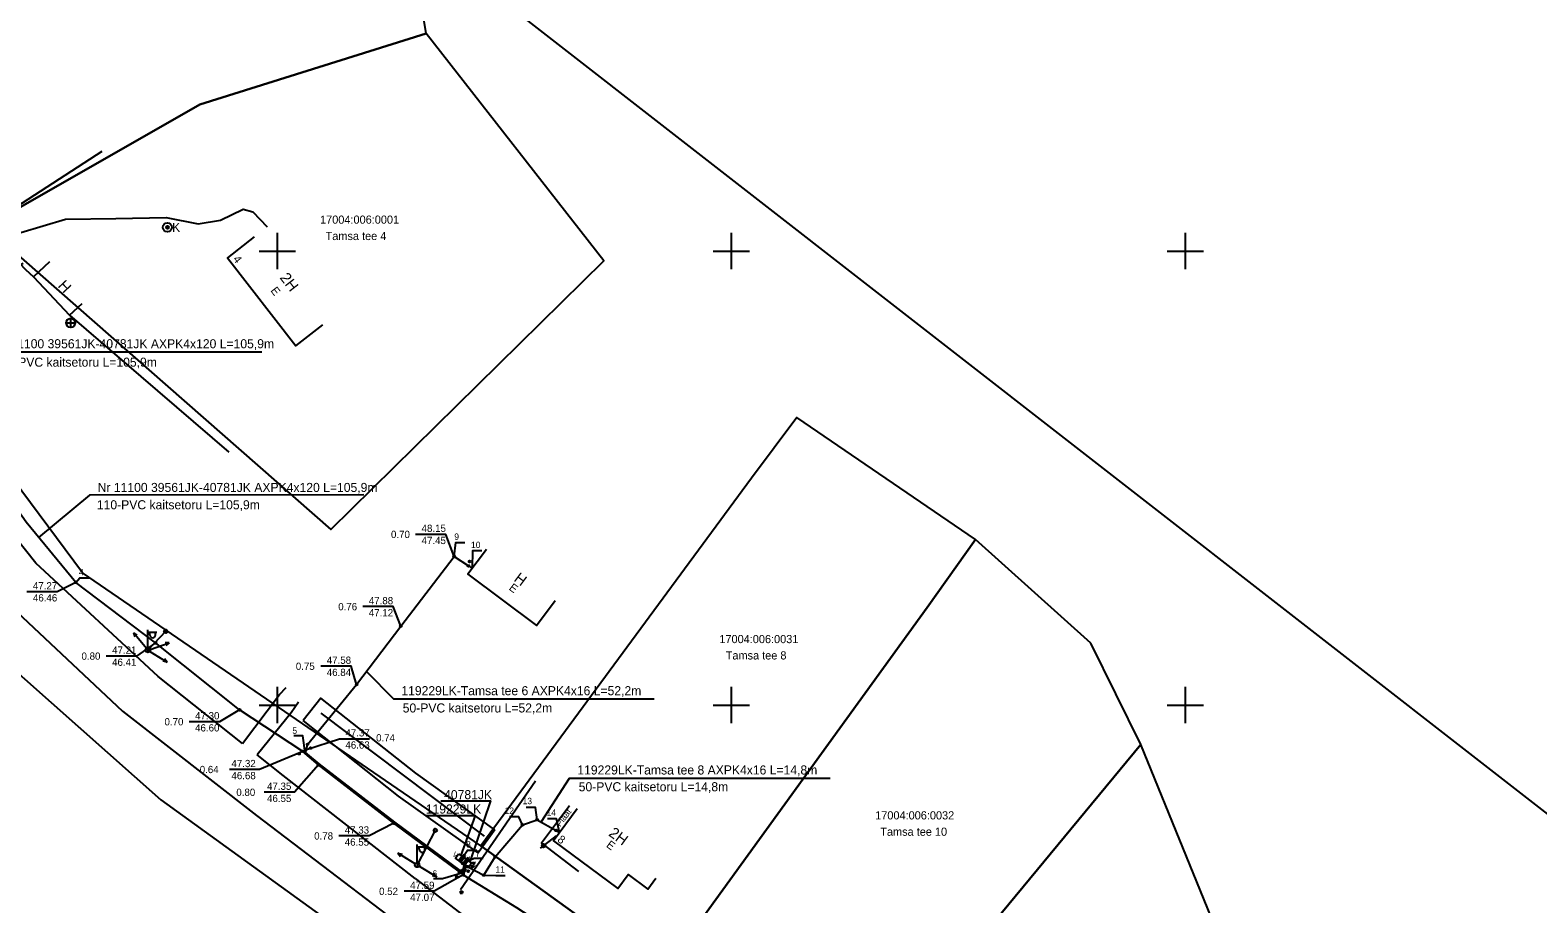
# Model space of a CAD drawing. Extents: x 643977 to 644381, y 6457457 to 6457867.
# Drawn here: x 644122.8 to 644288.8, y 6457628.1 to 6457724.3 of the extents above; entities that cross this region are included whole.
import ezdxf

# ---------------------------------------------------------------- set-up
doc = ezdxf.new("R2010")
doc.units = 0
for name, color, linetype in [('004 MPP EE @ 1 (1)', 7, 'Continuous'), ('005 MPO EE @ 1 (1)', 7, 'Continuous'), ('005 MPO EE @ 1 (2)', 7, 'Continuous'), ('007 PIIR EE', 7, 'Continuous'), ('007 PIIR1 EE', 7, 'Continuous'), ('010 TXT EE', 7, 'Continuous'), ('MOOTMPUNKT', 7, 'Continuous'), ('TEE', 7, 'Continuous'), ('TORU_NR', 7, 'Continuous'), ('UUS', 7, 'Continuous'), ('Veeprojekti jooned$0$0_Hoiatustekst', 7, 'Continuous'), ('VORK', 7, 'Continuous'), ('VORMISTUS', 7, 'Continuous'), ('WOUT EE', 7, 'Continuous')]:
    doc.layers.add(name, color=color, linetype=linetype)

msp = doc.modelspace()

# ---------------------------------------------------------------- linework, layer by layer
at = {"layer": '004 MPP EE @ 1 (1)'}
for p, q in [((644127.12, 6457692.94), (644144.69, 6457677.86)), ((644170.16, 6457629.51), (644170.16, 6457629.26)), ((644170.16, 6457629.51), (644170.41, 6457629.51)), ((644170.16, 6457629.26), (644170.41, 6457629.26)), ((644170.41, 6457629.51), (644170.41, 6457629.26))]:
    msp.add_line(p, q, dxfattribs=at)
msp.add_lwpolyline([(644130.68, 6457710.97), (644117.82, 6457702.64), (644119.64, 6457700.77), (644122.27, 6457697.99), (644123.17, 6457697.16)], dxfattribs=at)
at = {"layer": '005 MPO EE @ 1 (1)'}
for p, q in [((644135.76, 6457656.29), (644135.76, 6457658.29)), ((644137.72, 6457658.12), (644135.76, 6457656.04)), ((644135.76, 6457658.04), (644136.76, 6457658.04)), ((644135.99, 6457657.72), (644135.99, 6457658.04)), ((644136.6, 6457657.72), (644136.6, 6457658.04)), ((644167.41, 6457636.2), (644165.42, 6457632.39)), ((644165.42, 6457632.64), (644165.42, 6457634.64)), ((644165.42, 6457634.39), (644166.42, 6457634.39)), ((644165.65, 6457634.07), (644165.65, 6457634.39)), ((644166.26, 6457634.07), (644166.26, 6457634.39)), ((644170.35, 6457633.34), (644170, 6457632.86)), ((644170.57, 6457633.18), (644170.21, 6457632.7)), ((644170.81, 6457633.03), (644170.46, 6457632.55)), ((644171.03, 6457632.87), (644170.68, 6457632.39))]:
    msp.add_line(p, q, dxfattribs=at)
for points in [[(644166.35, 6457637.85), (644171.81, 6457637.85), (644170.19, 6457633.34)], [(644168.02, 6457639.46), (644173.5, 6457639.46), (644171.19, 6457632.63)]]:
    msp.add_lwpolyline(points, dxfattribs=at)
for points in [[(644169.98, 6457633.61), (644170.94, 6457632.9), (644170.58, 6457632.42), (644169.62, 6457633.13)], [(644170.44, 6457633.3), (644171.4, 6457632.6), (644171.05, 6457632.11), (644170.09, 6457632.82)]]:
    msp.add_lwpolyline(points, close=True, dxfattribs=at)
for centre, radius in [((644137.72, 6457658.12), 0.2), ((644135.76, 6457656.04), 0.25), ((644135.76, 6457656.04), 0.0234), ((644167.41, 6457636.2), 0.2), ((644165.42, 6457632.39), 0.25), ((644165.42, 6457632.39), 0.0234)]:
    msp.add_circle(centre, radius, dxfattribs=at)
for centre in [(644136.29, 6457657.72), (644165.96, 6457634.07)]:
    msp.add_arc(centre, 0.306, 180, 0, dxfattribs=at)
at = {"layer": '005 MPO EE @ 1 (2)'}
for points in [[(644146.19, 6457645.77), (644136.9, 6457653.15), (644123.42, 6457665.62), (644113.13, 6457678.52), (644106.19, 6457690.08), (644107.06, 6457690.75), (644119.77, 6457697.52), (644122.01, 6457698.68)], [(644097.36, 6457696.77), (644100.44, 6457690.48), (644108.83, 6457675.73), (644120.12, 6457661.42), (644132.97, 6457649.32), (644147.71, 6457637.83), (644162.19, 6457626.8)], [(644146.19, 6457645.77), (644150.27, 6457651.15), (644150.97, 6457651.94)], [(644152.36, 6457650.33), (644151.52, 6457649.15), (644147.79, 6457644.5)], [(644165.21, 6457630.91), (644150.65, 6457642.23), (644147.79, 6457644.5)], [(644182.18, 6457638.9), (644179.09, 6457634.77), (644183.17, 6457631.65)], [(644165.21, 6457630.91), (644174.34, 6457623.88), (644186.27, 6457614.62), (644201.04, 6457604.98), (644215.29, 6457597.39), (644225.39, 6457591.42), (644240.38, 6457581.38), (644253.47, 6457570.78), (644267.86, 6457559.31)]]:
    msp.add_lwpolyline(points, dxfattribs=at)
at = {"layer": '007 PIIR EE'}
for p, q in [((644134.16, 6457657.96), (644134.33, 6457657.51)), ((644134.16, 6457657.96), (644134.56, 6457657.71)), ((644135.6, 6457656.23), (644134.16, 6457657.96)), ((644136, 6457656.12), (644138.12, 6457656.86)), ((644138.12, 6457656.86), (644137.65, 6457656.85)), ((644138.12, 6457656.86), (644137.74, 6457656.57)), ((644135.98, 6457655.91), (644137.9, 6457654.74)), ((644137.9, 6457654.74), (644137.44, 6457654.85)), ((644137.9, 6457654.74), (644137.59, 6457655.1)), ((644163.29, 6457633.69), (644163.59, 6457633.32)), ((644163.29, 6457633.69), (644163.75, 6457633.58)), ((644165.21, 6457632.52), (644163.29, 6457633.69)), ((644165.64, 6457632.26), (644167.56, 6457631.09)), ((644167.56, 6457631.09), (644167.1, 6457631.2)), ((644167.56, 6457631.09), (644167.25, 6457631.46))]:
    msp.add_line(p, q, dxfattribs=at)
at = {"layer": '007 PIIR1 EE'}
for points in [[(644117.56, 6457701.26), (644118.53, 6457701.57), (644119.51, 6457701.72), (644121.77, 6457702.04), (644126.68, 6457703.53), (644132.24, 6457703.6), (644137.78, 6457703.72), (644141.28, 6457703.01), (644143.77, 6457703.42), (644146.25, 6457704.61), (644147.33, 6457704.32), (644148.9, 6457702.67)], [(644170.75, 6457632.71), (644170.64, 6457632.25), (644170.59, 6457631.82), (644170.29, 6457631.6), (644170.08, 6457631.62), (644162.86, 6457636.99), (644154.53, 6457643.4), (644152.81, 6457644.9), (644145.85, 6457649.47), (644136.59, 6457656.84), (644127.81, 6457663.51), (644122.37, 6457670.16), (644115.89, 6457679.24), (644110.22, 6457687.94), (644105.98, 6457693.61), (644105.49, 6457694.03), (644109.92, 6457695.7), (644115.67, 6457699.15), (644117.04, 6457700.73)], [(644170.75, 6457632.71), (644170.64, 6457632.25), (644170.59, 6457631.82), (644170.29, 6457631.6), (644170.08, 6457631.62), (644162.86, 6457636.99), (644154.53, 6457643.4), (644152.81, 6457644.9), (644145.85, 6457649.47), (644136.59, 6457656.84), (644127.81, 6457663.51), (644122.37, 6457670.16), (644115.89, 6457679.24), (644110.22, 6457687.94), (644105.98, 6457693.61), (644105.57, 6457694.06), (644109.92, 6457695.7), (644115.67, 6457699.15), (644117.04, 6457700.73)], [(644148.31, 6457688.88), (644118.1, 6457688.86), (644110.61, 6457696.12)], [(644159.55, 6457673.14), (644129.34, 6457673.12), (644123.73, 6457668.47)], [(644169.49, 6457666.35), (644168.57, 6457668.8), (644165.24, 6457668.8)], [(644170.75, 6457632.71), (644170.55, 6457632.25), (644170.45, 6457631.9), (644170.25, 6457631.76), (644170.13, 6457631.77), (644162.95, 6457637.11), (644154.63, 6457643.52), (644153.13, 6457644.79), (644153.21, 6457645.12), (644153.35, 6457645.67), (644158.75, 6457652.25), (644163.6, 6457658.7), (644169.49, 6457666.35), (644171.05, 6457665.32), (644171.49, 6457665.04)], [(644170.75, 6457632.71), (644170.55, 6457632.25), (644170.45, 6457631.9), (644170.25, 6457631.76), (644170.13, 6457631.77), (644162.95, 6457637.11), (644154.63, 6457643.52), (644153.13, 6457644.79), (644153.21, 6457645.12), (644153.35, 6457645.67), (644158.75, 6457652.25), (644163.6, 6457658.7), (644169.49, 6457666.35), (644171.05, 6457665.32), (644171.49, 6457665.04)], [(644127.81, 6457663.51), (644125.76, 6457662.47), (644122.43, 6457662.47)], [(644163.6, 6457658.7), (644162.76, 6457660.84), (644159.43, 6457660.84)], [(644136.59, 6457656.84), (644134.49, 6457655.39), (644131.15, 6457655.39)], [(644158.75, 6457652.25), (644158.13, 6457654.27), (644154.79, 6457654.27)], [(644159.84, 6457653.69), (644162.82, 6457650.67), (644191.52, 6457650.67)], [(644145.85, 6457649.47), (644143.63, 6457648.16), (644140.29, 6457648.16)], [(644153.21, 6457645.12), (644156.85, 6457646.27), (644160.18, 6457646.27)], [(644152.81, 6457644.9), (644148.06, 6457642.91), (644144.73, 6457642.91)], [(644154.53, 6457643.4), (644151.92, 6457640.4), (644148.58, 6457640.4)], [(644179.12, 6457637.19), (644182.2, 6457641.94), (644210.91, 6457641.94)], [(644162.86, 6457636.99), (644160.11, 6457635.58), (644156.77, 6457635.58)], [(644170.28, 6457633.02), (644170.31, 6457632.55), (644171, 6457632.19), (644172.75, 6457631.27), (644174, 6457633.28), (644177.01, 6457636.8), (644178.63, 6457637.37), (644180.72, 6457636.19), (644181.09, 6457635.97)], [(644170.28, 6457633.02), (644170.31, 6457632.55), (644171, 6457632.19), (644172.75, 6457631.27), (644174, 6457633.28), (644177.01, 6457636.8), (644178.63, 6457637.37), (644180.72, 6457636.19), (644181.09, 6457635.97)], [(644170.23, 6457633.48), (644170.74, 6457633.1)], [(644170.28, 6457633.02), (644170.48, 6457633.29)], [(644170.43, 6457633.52), (644170.72, 6457633.3)], [(644170.62, 6457633.56), (644170.7, 6457633.5)], [(644170.7, 6457633.17), (644171.21, 6457632.78)], [(644170.75, 6457632.71), (644170.95, 6457632.98)], [(644170.9, 6457633.21), (644171.19, 6457632.99)], [(644171.1, 6457633.25), (644171.18, 6457633.19)], [(644170.49, 6457631.29), (644167.3, 6457629.48), (644163.97, 6457629.48)], [(644170.75, 6457632.71), (644170.73, 6457632.25), (644170.67, 6457631.8), (644170.49, 6457631.29), (644176.35, 6457627.7), (644180.99, 6457624.7), (644187.78, 6457619.88), (644190.92, 6457616.92), (644195.57, 6457613.47), (644203.7, 6457608.17), (644207.66, 6457605.55), (644212.13, 6457602.91), (644212.43, 6457603.02), (644212.72, 6457603.52), (644212.73, 6457604.72)], [(644170.75, 6457632.71), (644170.73, 6457632.25), (644170.67, 6457631.8), (644170.49, 6457631.29), (644176.35, 6457627.7), (644180.99, 6457624.7), (644187.78, 6457619.88), (644190.92, 6457616.92), (644195.57, 6457613.47), (644203.7, 6457608.17), (644207.66, 6457605.55), (644212.13, 6457602.91), (644212.43, 6457603.02), (644212.72, 6457603.52), (644212.73, 6457604.72)]]:
    msp.add_lwpolyline(points, dxfattribs=at)
at = {"layer": '010 TXT EE'}
for p, q in [((644126.76, 6457692.1), (644127.76, 6457692.1)), ((644127.26, 6457691.6), (644127.26, 6457692.6))]:
    msp.add_line(p, q, dxfattribs=at)
msp.add_circle((644127.26, 6457692.1), 0.5, dxfattribs=at)
at = {"layer": 'Defpoints'}
for points in [[(644147.48, 6457701.57), (644144.53, 6457699.28), (644152.05, 6457689.57), (644155.03, 6457691.87)], [(644124.93, 6457698.81), (644123.17, 6457697.16), (644127.12, 6457692.94), (644128.51, 6457694.24)], [(644173.05, 6457667.14), (644171.01, 6457664.4), (644178.55, 6457658.78), (644180.6, 6457661.53)], [(644183.02, 6457638.58), (644180.41, 6457635.04), (644187.51, 6457629.8), (644188.64, 6457631.32), (644190.8, 6457629.73), (644191.7, 6457630.94)]]:
    msp.add_lwpolyline(points, dxfattribs=at)
at = {"layer": 'MOOTMPUNKT'}
for centre in [(644169.49, 6457666.35), (644171.05, 6457665.32), (644171.19, 6457665.82), (644127.81, 6457663.51), (644163.6, 6457658.7), (644136.59, 6457656.84), (644158.75, 6457652.25), (644145.85, 6457649.47), (644152.41, 6457644.64), (644152.81, 6457644.9), (644153.21, 6457645.12), (644153.35, 6457645.67), (644153.68, 6457645.26), (644154.53, 6457643.4), (644162.86, 6457636.99), (644177.01, 6457636.8), (644178.63, 6457637.37), (644180.72, 6457636.19), (644170.46, 6457633.26), (644170.92, 6457632.95), (644174, 6457633.28), (644170.08, 6457631.62), (644170.29, 6457631.6), (644170.49, 6457631.29), (644170.52, 6457631.77), (644170.59, 6457631.82), (644170.67, 6457631.8), (644170.73, 6457632.25), (644171, 6457632.19), (644171.04, 6457631.7), (644171.5, 6457632.2), (644171.63, 6457632.57), (644172.75, 6457631.27), (644169.78, 6457631.07)]:
    msp.add_circle(centre, 0.1, dxfattribs=at)
at = {"layer": 'TEE'}
for points in [[(644084.27, 6457738.29), (644105.62, 6457695.4), (644117.87, 6457702.68), (644141.47, 6457716.14), (644166.4, 6457723.98), (644161.44, 6457753.91), (644160.79, 6457756.77), (644152.83, 6457754.95), (644133.56, 6457751.83), (644087.35, 6457749.32), (644082.35, 6457742.69)], [(644141.47, 6457716.14), (644117.87, 6457702.68), (644155.89, 6457669.35), (644185.98, 6457698.94), (644166.4, 6457723.98)], [(644226.91, 6457668.24), (644207.22, 6457681.69), (644202.24, 6457674.99), (644172.44, 6457634.51), (644192.23, 6457620.22), (644221.58, 6457660.75)], [(644239.59, 6457656.82), (644226.91, 6457668.24), (644221.58, 6457660.75), (644192.23, 6457620.22), (644212.32, 6457605.7), (644228.29, 6457625.32), (644245.1, 6457645.66)], [(644249.59, 6457612.49), (644255.15, 6457620.97), (644245.1, 6457645.66), (644228.29, 6457625.32), (644212.32, 6457605.7), (644213.34, 6457605.08), (644233.94, 6457592.97)]]:
    msp.add_lwpolyline(points, close=True, dxfattribs=at)
msp.add_lwpolyline([(644119.21, 6457655.5), (644137.18, 6457639.57), (644176.94, 6457610.8), (644193.44, 6457599.42), (644220.94, 6457583.42), (644258.83, 6457557.54), (644299.64, 6457526.51), (644330.13, 6457505.12), (644351.66, 6457500.83), (644373.13, 6457501.25), (644368.81, 6457508.24), (644366.6, 6457513.63), (644352.78, 6457513.35), (644335.16, 6457516.88), (644304.29, 6457538.7), (644233.94, 6457592.97), (644213.34, 6457605.08), (644212.32, 6457605.7), (644192.23, 6457620.22), (644172.44, 6457634.51), (644128.57, 6457664.58), (644105.62, 6457695.4)], dxfattribs=at)
at = {"layer": 'TORU_NR'}
for p, q in [((644154.79, 6457649.12), (644172.78, 6457635.54)), ((644170.19, 6457629.67), (644178.45, 6457641.65))]:
    msp.add_line(p, q, dxfattribs=at)
for points in [[(644173.95, 6457636.27), (644165.27, 6457642.48), (644154.82, 6457650.75), (644152.87, 6457648.28)], [(644173.95, 6457636.27), (644172.12, 6457633.71), (644163.37, 6457639.96), (644152.87, 6457648.28)]]:
    msp.add_lwpolyline(points, dxfattribs=at)
at = {"layer": 'UUS'}
for points in [[(644169.49, 6457666.35), (644169.67, 6457667.92), (644170.67, 6457667.92)], [(644171.49, 6457665.04), (644171.55, 6457667.03), (644172.55, 6457667.03)], [(644127.81, 6457663.51), (644128.28, 6457664), (644129.28, 6457664)], [(644153.08, 6457644.78), (644152.83, 6457646.6), (644151.83, 6457646.6)], [(644178.63, 6457637.37), (644178.43, 6457638.71), (644177.43, 6457638.71)], [(644177.01, 6457636.8), (644176.59, 6457637.7), (644175.59, 6457637.7)], [(644181.09, 6457635.97), (644180.77, 6457637.47), (644179.77, 6457637.47)], [(644170.28, 6457633.02), (644170.97, 6457634.03), (644171.97, 6457634.03)], [(644170.75, 6457632.71), (644171.68, 6457633.13), (644172.68, 6457633.13)], [(644170.44, 6457631.51), (644168.2, 6457630.87), (644167.2, 6457630.87)], [(644172.75, 6457631.27), (644174.09, 6457631.24), (644175.09, 6457631.24)]]:
    msp.add_lwpolyline(points, dxfattribs=at)
at = {"layer": 'Veeprojekti jooned$0$0_Hoiatustekst'}
msp.add_line((644180.72, 6457635.58), (644178.95, 6457634.22), dxfattribs=at)
msp.add_line((644180.72, 6457635.58), (644178.95, 6457634.22), dxfattribs=at)
for radius in [0.199, 0.199, 0.19, 0.19, 0.18, 0.18, 0.171, 0.171, 0.162, 0.162, 0.152, 0.152, 0.143, 0.143, 0.133, 0.133, 0.124, 0.124, 0.114, 0.114, 0.105, 0.0953, 0.105, 0.0953, 0.0858, 0.0858, 0.0763, 0.0763, 0.0669, 0.0669, 0.0574, 0.0574, 0.0479, 0.0479, 0.0385, 0.0385, 0.029, 0.029, 0.0195, 0.0195, 0.0101, 0.0101, 0.00061, 0.00061]:
    msp.add_circle((644179.34, 6457634.52), radius, dxfattribs=at)
at = {"layer": 'VORK'}
for p, q in [((644150, 6457702), (644150, 6457698)), ((644200, 6457702), (644200, 6457698)), ((644250, 6457702), (644250, 6457698)), ((644148, 6457700), (644152, 6457700)), ((644198, 6457700), (644202, 6457700)), ((644248, 6457700), (644252, 6457700)), ((644150, 6457652), (644150, 6457648)), ((644200, 6457652), (644200, 6457648)), ((644250, 6457652), (644250, 6457648)), ((644148, 6457650), (644152, 6457650)), ((644198, 6457650), (644202, 6457650)), ((644248, 6457650), (644252, 6457650))]:
    msp.add_line(p, q, dxfattribs=at)
at = {"layer": 'VORMISTUS'}
msp.add_lwpolyline([(644374.21, 6457572.35), (644287.82, 6457461.37), (644045.28, 6457650.18), (644131.67, 6457761.15)], close=True, dxfattribs=at)
at = {"layer": 'WOUT EE'}
for radius in [0.5, 0.15, 0.125, 0.1, 0.075, 0.05, 0.025]:
    msp.add_circle((644137.91, 6457702.62), radius, dxfattribs=at)

# ---------------------------------------------------------------- texts
at = {"layer": '005 MPO EE @ 1 (1)'}
for s, p in [('40781JK', (644168.38, 6457639.63)), ('119229LK', (644166.36, 6457638.05))]:
    msp.add_text(s, height=1, dxfattribs=at).set_placement(p)
for p in [(644169.23, 6457633.45), (644171.46, 6457632.36)]:
    msp.add_text('V', height=0.56, rotation=320.1944, dxfattribs=at).set_placement(p)
at = {"layer": '005 MPO EE @ 1 (2)'}
msp.add_text('Plaat', height=0.7, rotation=53.1502, dxfattribs=at).set_placement((644181.17, 6457636.54))
at = {"layer": '007 PIIR1 EE'}
for s, height, p in [('Nr 11100 39561JK-40781JK AXPK4x120 L=105,9m', 1, (644118.84, 6457689.3)), ('110-PVC kaitsetoru L=105,9m', 1, (644118.8, 6457687.27)), ('Nr 11100 39561JK-40781JK AXPK4x120 L=105,9m', 1, (644130.23, 6457673.47)), ('110-PVC kaitsetoru L=105,9m', 1, (644130.14, 6457671.56)), ('48.15', 0.8, (644165.9, 6457669.07)), ('0.70', 0.8, (644162.53, 6457668.4)), ('47.45', 0.8, (644165.9, 6457667.73)), ('47.27', 0.8, (644123.1, 6457662.74)), ('46.46', 0.8, (644123.1, 6457661.41)), ('0.76', 0.8, (644156.72, 6457660.44)), ('47.88', 0.8, (644160.09, 6457661.1)), ('47.12', 0.8, (644160.09, 6457659.77)), ('47.21', 0.8, (644131.82, 6457655.65)), ('0.80', 0.8, (644128.45, 6457654.99)), ('46.41', 0.8, (644131.82, 6457654.32)), ('0.75', 0.8, (644152.05, 6457653.87)), ('47.58', 0.8, (644155.46, 6457654.54)), ('46.84', 0.8, (644155.46, 6457653.2)), ('119229LK-Tamsa tee 6 AXPK4x16 L=52,2m', 1, (644163.67, 6457651.08)), ('50-PVC kaitsetoru L=52,2m', 1, (644163.82, 6457649.18)), ('0.70', 0.8, (644137.59, 6457647.76)), ('47.30', 0.8, (644140.96, 6457648.42)), ('46.60', 0.8, (644140.96, 6457647.09)), ('47.37', 0.8, (644157.51, 6457646.54)), ('0.74', 0.8, (644160.89, 6457645.99)), ('46.63', 0.8, (644157.51, 6457645.2)), ('0.64', 0.8, (644141.47, 6457642.5)), ('47.32', 0.8, (644144.96, 6457643.16)), ('119229LK-Tamsa tee 8 AXPK4x16 L=14,8m', 1, (644183.05, 6457642.35)), ('46.68', 0.8, (644144.96, 6457641.83)), ('47.35', 0.8, (644148.88, 6457640.66)), ('50-PVC kaitsetoru L=14,8m', 1, (644183.2, 6457640.5)), ('0.80', 0.8, (644145.5, 6457639.99)), ('46.55', 0.8, (644148.88, 6457639.32)), ('47.33', 0.8, (644157.44, 6457635.84)), ('0.78', 0.8, (644154.07, 6457635.18)), ('46.55', 0.8, (644157.44, 6457634.51)), ('0.52', 0.8, (644161.22, 6457629.08)), ('47.59', 0.8, (644164.64, 6457629.75)), ('47.07', 0.8, (644164.64, 6457628.42))]:
    msp.add_text(s, height=height, dxfattribs=at).set_placement(p)
at = {"layer": 'Defpoints'}
for s, height, rotation, p in [('4', 0.9, 307.7539, (644145.08, 6457699.1)), ('2H', 1.2, 307.7539, (644150.23, 6457697.05)), ('H', 1.2, 313.0906, (644125.78, 6457696.13)), ('E', 0.9, 307.7539, (644149.22, 6457695.64)), ('H', 1.2, 323.3459, (644175.98, 6457663.73)), ('E', 0.9, 323.3459, (644175.44, 6457662.76)), ('2H', 1.2, 323.5871, (644186.41, 6457635.68)), ('8', 0.9, 323.5871, (644180.78, 6457635.02)), ('E', 0.9, 323.5871, (644186.16, 6457634.43))]:
    msp.add_text(s, height=height, rotation=rotation, dxfattribs=at).set_placement(p)
at = {"layer": 'TEE'}
for s, p in [('17004:006:0001', (644154.72, 6457703.02)), ('Tamsa tee 4', (644155.33, 6457701.22)), ('17004:006:0031', (644198.69, 6457656.82)), ('Tamsa tee 8', (644199.39, 6457655.02)), ('17004:006:0032', (644215.85, 6457637.4)), ('Tamsa tee 10', (644216.41, 6457635.6))]:
    msp.add_text(s, height=0.9, dxfattribs=at).set_placement(p)
at = {"layer": 'UUS'}
for s, p in [(' 9', (644169.24, 6457668.2)), (' 10', (644171.08, 6457667.29)), (' 4', (644127.91, 6457664.29)), (' 5', (644151.41, 6457646.83)), (' 13', (644176.76, 6457639.08)), (' 12', (644174.78, 6457638.01)), (' 14', (644179.4, 6457637.8)), (' 8', (644170.54, 6457634.3)), (' 7', (644171.57, 6457633.28)), (' 6', (644166.84, 6457631.09)), (' 11', (644173.77, 6457631.53))]:
    msp.add_text(s, height=0.7, dxfattribs=at).set_placement(p)
at = {"layer": 'WOUT EE'}
msp.add_text('K', height=1, dxfattribs=at).set_placement((644138.43, 6457702.11))

doc.saveas('drawing.dxf')
